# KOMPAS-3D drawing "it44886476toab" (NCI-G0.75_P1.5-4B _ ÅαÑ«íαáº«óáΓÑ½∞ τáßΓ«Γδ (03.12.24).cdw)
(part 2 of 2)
  Кривая без истории:10762
  Кривая без истории:10763
  Кривая без истории:10764
  Кривая без истории:10765
  Кривая без истории:10766
  Кривая без истории:10767
  Кривая без истории:10768
  Кривая без истории:10769
  Кривая без истории:10770
  Кривая без истории:10771
  Кривая без истории:10772
  Кривая без истории:10773
  Кривая без истории:10774
  Кривая без истории:10775
  Кривая без истории:10776
  Кривая без истории:10777
  Кривая без истории:10778
  Кривая без истории:10779
  Кривая без истории:10780
  Кривая без истории:10781
  Кривая без истории:10782
  Кривая без истории:10783
  Кривая без истории:10784
  Кривая без истории:10785
  Кривая без истории:10786
  Кривая без истории:10787
  Кривая без истории:10788
  Кривая без истории:10789
  Кривая без истории:10790
  Кривая без истории:10791
  Кривая без истории:10792
  Кривая без истории:10793
  Кривая без истории:10794
  Кривая без истории:10795
  Кривая без истории:10796
  Кривая без истории:10797
  Кривая без истории:10798
  Кривая без истории:10799
  Кривая без истории:10800
  Кривая без истории:10801
  Кривая без истории:10802
  Кривая без истории:10803
  Кривая без истории:10804
  Кривая без истории:10805
  Кривая без истории:10806
  Кривая без истории:10807
  Кривая без истории:10808
  Кривая без истории:10809
  Кривая без истории:10810
  Кривая без истории:10811
  Кривая без истории:10812
  Кривая без истории:10813
  Кривая без истории:10814
  Кривая без истории:10815
  Кривая без истории:10816
  Кривая без истории:10817
  Кривая без истории:10818
  Кривая без истории:10819
  Кривая без истории:10820
  Кривая без истории:10821
  Кривая без истории:10822
  Кривая без истории:10823
  Кривая без истории:10824
  Кривая без истории:10825
  Кривая без истории:10826
  Кривая без истории:10827
  Кривая без истории:10828
  Кривая без истории:10829
  Кривая без истории:10830
  Кривая без истории:10831
  Кривая без истории:10832
  Кривая без истории:10833
  Кривая без истории:10834
  Кривая без истории:10835
  Кривая без истории:10836
  Кривая без истории:10837
  Кривая без истории:10838
  Кривая без истории:10839
  Кривая без истории:10840
  Кривая без истории:10841
  Кривая без истории:10842
  Кривая без истории:10843
  Кривая без истории:10844
  Кривая без истории:10845
  Кривая без истории:10846
  Кривая без истории:10847
  Кривая без истории:10848
  Кривая без истории:10849
  Кривая без истории:10850
  Кривая без истории:10851
  Кривая без истории:10852
  Кривая без истории:10853
  Кривая без истории:10854
  Кривая без истории:10855
  Кривая без истории:10856
  Кривая без истории:10857
  Кривая без истории:10858
  Кривая без истории:10859
  Кривая без истории:10860
  Кривая без истории:10861
  Кривая без истории:10862
  Кривая без истории:10863
  Кривая без истории:10864
  Кривая без истории:10865
  Кривая без истории:10866
  Кривая без истории:10867
  Кривая без истории:10868
  Кривая без истории:10869
  Кривая без истории:10870
  Кривая без истории:10871
  Кривая без истории:10872
  Кривая без истории:10873
  Кривая без истории:10874
  Кривая без истории:10875
  Кривая без истории:10876
  Кривая без истории:10877
  Кривая без истории:10878
  Кривая без истории:10879
  Кривая без истории:10880
  Кривая без истории:10881
  Кривая без истории:10882
  Кривая без истории:10883
  Кривая без истории:10884
  Кривая без истории:10885
  Кривая без истории:10886
  Кривая без истории:10887
  Кривая без истории:10888
  Кривая без истории:10889
  Кривая без истории:10890
  Кривая без истории:10891
  Кривая без истории:10892
  Кривая без истории:10893
  Кривая без истории:10894
  Кривая без истории:10895
  Кривая без истории:10896
  Кривая без истории:10897
  Кривая без истории:10898
  Кривая без истории:10899
  Кривая без истории:10900
  Кривая без истории:10901
  Кривая без истории:10902
  Кривая без истории:10903
  Кривая без истории:10904
  Кривая без истории:10905
  Кривая без истории:10906
  Кривая без истории:10907
  Кривая без истории:10908
  Кривая без истории:10909
  Кривая без истории:10910
  Кривая без истории:10911
  Кривая без истории:10912
  Кривая без истории:10913
  Кривая без истории:10914
  Кривая без истории:10915
  Кривая без истории:10916
  Кривая без истории:10917
  Кривая без истории:10918
  Кривая без истории:10919
  Кривая без истории:10920
  Кривая без истории:10921
  Кривая без истории:10922
  Кривая без истории:10923
  Кривая без истории:10924
  Кривая без истории:10925
  Кривая без истории:10926
  Кривая без истории:10927
  Кривая без истории:10928
  Кривая без истории:10929
  Кривая без истории:10930
  Кривая без истории:10931
  Кривая без истории:10932
  Кривая без истории:10933
  Кривая без истории:10934
  Кривая без истории:10935
  Кривая без истории:10936
  Кривая без истории:10937
  Кривая без истории:10938
  Кривая без истории:10939
  Кривая без истории:10940
  Кривая без истории:10941
  Кривая без истории:10942
  Кривая без истории:10943
  Кривая без истории:10944
  Кривая без истории:10945
  Кривая без истории:10946
  Кривая без истории:10947
  Кривая без истории:10948
  Кривая без истории:10949
  Кривая без истории:10950
  Кривая без истории:10951
  Кривая без истории:10952
  Кривая без истории:10953
  Кривая без истории:10954
  Кривая без истории:10955
  Кривая без истории:10956
  Кривая без истории:10957
  Кривая без истории:10958
  Кривая без истории:10959
  Кривая без истории:10960
  Кривая без истории:10961
  Кривая без истории:10962
  Кривая без истории:10963
  Кривая без истории:10964
  Кривая без истории:10965
  Кривая без истории:10966
  Кривая без истории:10967
  Кривая без истории:10968
  Кривая без истории:10969
  Кривая без истории:10970
  Кривая без истории:10971
  Кривая без истории:10972
  Кривая без истории:10973
  Кривая без истории:10974
  Кривая без истории:10975
  Кривая без истории:10976
  Кривая без истории:10977
  Кривая без истории:10978
  Кривая без истории:10979
  Кривая без истории:10980
  Кривая без истории:10981
  Кривая без истории:10982
  Кривая без истории:10983
  Кривая без истории:10984
  Кривая без истории:10985
  Кривая без истории:10986
  Кривая без истории:10987
  Кривая без истории:10988
  Кривая без истории:10989
  Кривая без истории:10990
  Кривая без истории:10991
  Кривая без истории:10992
  Кривая без истории:10993
  Кривая без истории:10994
  Кривая без истории:10995
  Кривая без истории:10996
  Кривая без истории:10997
  Кривая без истории:10998
  Кривая без истории:10999
  Кривая без истории:11000
  Кривая без истории:11001
  Кривая без истории:11002
  Кривая без истории:11003
  Кривая без истории:11004
  Кривая без истории:11005
  Кривая без истории:11006
  Кривая без истории:11007
  Кривая без истории:11008
  Кривая без истории:11009
  Кривая без истории:11010
  Кривая без истории:11011
  Кривая без истории:11012
  Кривая без истории:11013
  Кривая без истории:11014
  Кривая без истории:11015
  Кривая без истории:11016
  Кривая без истории:11017
  Кривая без истории:11018
  Кривая без истории:11019
  Кривая без истории:11020
  Кривая без истории:11021
  Кривая без истории:11022
  Кривая без истории:11023
  Кривая без истории:11024
  Кривая без истории:11025
  Кривая без истории:11026
  Кривая без истории:11027
  Кривая без истории:11028
  Кривая без истории:11029
  Кривая без истории:11030
  Кривая без истории:11031
  Кривая без истории:11032
  Кривая без истории:11033
  Кривая без истории:11034
  Кривая без истории:11035
  Кривая без истории:11036
  Кривая без истории:11037
  Кривая без истории:11038
  Кривая без истории:11039
  Кривая без истории:11040
  Кривая без истории:11041
  Кривая без истории:11042
  Кривая без истории:11043
  Кривая без истории:11044
  Кривая без истории:11045
  Кривая без истории:11046
  Кривая без истории:11047
  Кривая без истории:11048
  Кривая без истории:11049
  Кривая без истории:11050
  Кривая без истории:11051
  Кривая без истории:11052
  Кривая без истории:11053
  Кривая без истории:11054
  Кривая без истории:11055
  Кривая без истории:11056
  Кривая без истории:11057
  Кривая без истории:11058
  Кривая без истории:11059
  Кривая без истории:11060
  Кривая без истории:11061
  Кривая без истории:11062
  Кривая без истории:11063
  Кривая без истории:11064
  Кривая без истории:11065
  Кривая без истории:11066
  Кривая без истории:11067
  Кривая без истории:11068
  Кривая без истории:11069
  Кривая без истории:11070
  Кривая без истории:11071
  Кривая без истории:11072
  Кривая без истории:11073
  Кривая без истории:11074
  Кривая без истории:11075
  Кривая без истории:11076
  Кривая без истории:11077
  Кривая без истории:11078
  Кривая без истории:11079
  Кривая без истории:11080
  Кривая без истории:11081
  Кривая без истории:11082
  Кривая без истории:11083
  Кривая без истории:11084
  Кривая без истории:11085
  Кривая без истории:11086
  Кривая без истории:11087
  Кривая без истории:11088
  Кривая без истории:11089
  Кривая без истории:11090
  Кривая без истории:11091
  Кривая без истории:11092
  Кривая без истории:11093
  Кривая без истории:11094
  Кривая без истории:11095
  Кривая без истории:11096
  Кривая без истории:11097
  Кривая без истории:11098
  Кривая без истории:11099
  Кривая без истории:11100
  Кривая без истории:11101
  Кривая без истории:11102
  Кривая без истории:11103
  Кривая без истории:11104
  Кривая без истории:11105
  Кривая без истории:11106
  Кривая без истории:11107
  Кривая без истории:11108
  Кривая без истории:11109
  Кривая без истории:11110
  Кривая без истории:11111
  Кривая без истории:11112
  Кривая без истории:11113
  Кривая без истории:11114
  Кривая без истории:11115
  Кривая без истории:11116
  Кривая без истории:11117
  Кривая без истории:11118
  Кривая без истории:11119
  Кривая без истории:11120
  Кривая без истории:11121
  Кривая без истории:11122
  Кривая без истории:11123
  Кривая без истории:11124
  Кривая без истории:11125
  Кривая без истории:11126
  Кривая без истории:11127
  Кривая без истории:11128
  Кривая без истории:11129
  Кривая без истории:11130
  Кривая без истории:11131
  Кривая без истории:11132
  Кривая без истории:11133
  Кривая без истории:11134
  Кривая без истории:11135
  Кривая без истории:11136
  Кривая без истории:11137
  Кривая без истории:11138
  Кривая без истории:11139
  Кривая без истории:11140
  Кривая без истории:11141
  Кривая без истории:11142
  Кривая без истории:11143
  Кривая без истории:11144
  Кривая без истории:11145
  Кривая без истории:11146
  Кривая без истории:11147
  Кривая без истории:11148
  Кривая без истории:11149
  Кривая без истории:11150
  Кривая без истории:11151
  Кривая без истории:11152
  Кривая без истории:11153
  Кривая без истории:11154
  Кривая без истории:11155
  Кривая без истории:11156
  Кривая без истории:11157
  Кривая без истории:11158
  Кривая без истории:11159
  Кривая без истории:11160
  Кривая без истории:11161
  Кривая без истории:11162
  Кривая без истории:11163
  Кривая без истории:11164
  Кривая без истории:11165
  Кривая без истории:11166
  Кривая без истории:11167
  Кривая без истории:11168
  Кривая без истории:11169
  Кривая без истории:11170
  Кривая без истории:11171
  Кривая без истории:11172
  Кривая без истории:11173
  Кривая без истории:11174
  Кривая без истории:11175
  Кривая без истории:11176
  Кривая без истории:11177
  Кривая без истории:11178
  Кривая без истории:11179
  Кривая без истории:11180
  Кривая без истории:11181
  Кривая без истории:11182
  Кривая без истории:11183
  Кривая без истории:11184
  Кривая без истории:11185
  Кривая без истории:11186
  Кривая без истории:11187
  Кривая без истории:11188
  Кривая без истории:11189
  Кривая без истории:11190
  Кривая без истории:11191
  Кривая без истории:11192
  Кривая без истории:11193
  Кривая без истории:11194
  Кривая без истории:11195
  Кривая без истории:11196
  Кривая без истории:11197
  Кривая без истории:11198
  Кривая без истории:11199
  Кривая без истории:11200
  Кривая без истории:11201
  Кривая без истории:11202
  Кривая без истории:11203
  Кривая без истории:11204
  Кривая без истории:11205
  Кривая без истории:11206
  Кривая без истории:11207
  Кривая без истории:11208
  Кривая без истории:11209
  Кривая без истории:11210
  Кривая без истории:11211
  Кривая без истории:11212
  Кривая без истории:11213
  Кривая без истории:11214
  Кривая без истории:11215
  Кривая без истории:11216
  Кривая без истории:11217
  Кривая без истории:11218
  Кривая без истории:11219
  Кривая без истории:11220
  Кривая без истории:11221
  Кривая без истории:11222
  Кривая без истории:11223
  Кривая без истории:11224
  Кривая без истории:11225
  Кривая без истории:11226
  Кривая без истории:11227
  Кривая без истории:11228
  Кривая без истории:11229
  Кривая без истории:11230
  Кривая без истории:11231
  Кривая без истории:11232
  Кривая без истории:11233
  Кривая без истории:11234
  Кривая без истории:11235
  Кривая без истории:11236
  Кривая без истории:11237
  Кривая без истории:11238
  Кривая без истории:11239
  Кривая без истории:11240
  Кривая без истории:11241
  Кривая без истории:11242
  Кривая без истории:11243
  Кривая без истории:11244
  Кривая без истории:11245
  Кривая без истории:11246
  Кривая без истории:11247
  Кривая без истории:11248
  Кривая без истории:11249
  Кривая без истории:11250
  Кривая без истории:11251
  Кривая без истории:11252
  Кривая без истории:11253
  Кривая без истории:11254
  Кривая без истории:11255
  Кривая без истории:11256
  Кривая без истории:11257
  Кривая без истории:11258
  Кривая без истории:11259
  Кривая без истории:11260
  Кривая без истории:11261
  Кривая без истории:11262
  Кривая без истории:11263
  Кривая без истории:11264
  Кривая без истории:11265
  Кривая без истории:11266
  Кривая без истории:11267
  Кривая без истории:11268
  Кривая без истории:11269
  Кривая без истории:11270
  Кривая без истории:11271
  Кривая без истории:11272
  Кривая без истории:11273
  Кривая без истории:11274
  Кривая без истории:11275
  Кривая без истории:11276
  Кривая без истории:11277
  Кривая без истории:11278
  Кривая без истории:11279
  Кривая без истории:11280
  Кривая без истории:11281
  Кривая без истории:11282
  Кривая без истории:11283
  Кривая без истории:11284
  Кривая без истории:11285
  Кривая без истории:11286
  Кривая без истории:11287
  Кривая без истории:11288
  Кривая без истории:11289
  Кривая без истории:11290
  Кривая без истории:11291
  Кривая без истории:11292
  Кривая без истории:11293
  Кривая без истории:11294
  Кривая без истории:11295
  Кривая без истории:11296
  Кривая без истории:11297
  Кривая без истории:11298
  Кривая без истории:11299
  Кривая без истории:11300
  Кривая без истории:11301
  Кривая без истории:11302
  Кривая без истории:11303
  Кривая без истории:11304
  Кривая без истории:11305
  Кривая без истории:11306
  Кривая без истории:11307
  Кривая без истории:11308
  Кривая без истории:11309
  Кривая без истории:11310
  Кривая без истории:11311
  Кривая без истории:11312
  Кривая без истории:11313
  Кривая без истории:11314
  Кривая без истории:11315
  Кривая без истории:11316
  Кривая без истории:11317
  Кривая без истории:11318
  Кривая без истории:11319
  Кривая без истории:11320
  Кривая без истории:11321
  Кривая без истории:11322
  Кривая без истории:11323
  Кривая без истории:11324
  Кривая без истории:11325
  Кривая без истории:11326
  Кривая без истории:11327
  Кривая без истории:11328
  Кривая без истории:11329
  Кривая без истории:11330
  Кривая без истории:11331
  Кривая без истории:11332
  Кривая без истории:11333
  Кривая без истории:11334
  Кривая без истории:11335
  Кривая без истории:11336
  Кривая без истории:11337
  Кривая без истории:11338
  Кривая без истории:11339
  Кривая без истории:11340
  Кривая без истории:11341
  Кривая без истории:11342
  Кривая без истории:11343
  Кривая без истории:11344
  Кривая без истории:11345
  Кривая без истории:11346
  Кривая без истории:11347
  Кривая без истории:11348
  Кривая без истории:11349
  Кривая без истории:11350
  Кривая без истории:11351
  Кривая без истории:11352
  Кривая без истории:11353
  Кривая без истории:11354
  Кривая без истории:11355
  Кривая без истории:11356
  Кривая без истории:11357
  Кривая без истории:11358
  Кривая без истории:11359
  Кривая без истории:11360
  Кривая без истории:11361
  Кривая без истории:11362
  Кривая без истории:11363
  Кривая без истории:11364
  Кривая без истории:11365
  Кривая без истории:11366
  Кривая без истории:11367
  Кривая без истории:11368
  Кривая без истории:11369
  Кривая без истории:11370
  Кривая без истории:11371
  Кривая без истории:11372
  Кривая без истории:11373
  Кривая без истории:11374
  Кривая без истории:11375
  Кривая без истории:11376
  Кривая без истории:11377
  Кривая без истории:11378
  Кривая без истории:11379
  Кривая без истории:11380
  Кривая без истории:11381
  Кривая без истории:11382
  Кривая без истории:11383
  Кривая без истории:11384
  Кривая без истории:11385
  Кривая без истории:11386
  Кривая без истории:11387
  Кривая без истории:11388
  Кривая без истории:11389
  Кривая без истории:11390
  Кривая без истории:11391
  Кривая без истории:11392
  Кривая без истории:11393
  Кривая без истории:11394
  Кривая без истории:11395
  Кривая без истории:11396
  Кривая без истории:11397
  Кривая без истории:11398
  Кривая без истории:11399
  Кривая без истории:11400
  Кривая без истории:11401
  Кривая без истории:11402
  Кривая без истории:11403
  Кривая без истории:11404
  Кривая без истории:11405
  Кривая без истории:11406
  Кривая без истории:11407
  Кривая без истории:11408
  Кривая без истории:11409
  Кривая без истории:11410
  Кривая без истории:11411
  Кривая без истории:11412
  Кривая без истории:11413
  Кривая без истории:11414
  Кривая без истории:11415
  Кривая без истории:11416
  Кривая без истории:11417
  Кривая без истории:11418
  Кривая без истории:11419
  Кривая без истории:11420
  Кривая без истории:11421
  Кривая без истории:11422
  Кривая без истории:11423
  Кривая без истории:11424
  Кривая без истории:11425
  Кривая без истории:11426
  Кривая без истории:11427
  Кривая без истории:11428
  Кривая без истории:11429
  Кривая без истории:11430
  Кривая без истории:11431
  Кривая без истории:11432
  Кривая без истории:11433
  Кривая без истории:11434
  Кривая без истории:11435
  Кривая без истории:11436
  Кривая без истории:11437
  Кривая без истории:11438
  Кривая без истории:11439
  Кривая без истории:11440
  Кривая без истории:11441
  Кривая без истории:11442
  Кривая без истории:11443
  Кривая без истории:11444
  Кривая без истории:11445
  Кривая без истории:11446
  Кривая без истории:11447
  Кривая без истории:11448
  Кривая без истории:11449
  Кривая без истории:11450
  Кривая без истории:11451
  Кривая без истории:11452
  Кривая без истории:11453
  Кривая без истории:11454
  Кривая без истории:11455
  Кривая без истории:11456
  Кривая без истории:11457
  Кривая без истории:11458
  Кривая без истории:11459
  Кривая без истории:11460
  Кривая без истории:11461
  Кривая без истории:11462
  Кривая без истории:11463
  Кривая без истории:11464
  Кривая без истории:11465
  Кривая без истории:11466
  Кривая без истории:11467
  Кривая без истории:11468
  Кривая без истории:11469
  Кривая без истории:11470
  Кривая без истории:11471
  Кривая без истории:11472
  Кривая без истории:11473
  Кривая без истории:11474
  Кривая без истории:11475
  Кривая без истории:11476
  Кривая без истории:11477
  Кривая без истории:11478
  Кривая без истории:11479
  Кривая без истории:11480
  Кривая без истории:11481
  Кривая без истории:11482
  Кривая без истории:11483
  Кривая без истории:11484
  Кривая без истории:11485
  Кривая без истории:11486
  Кривая без истории:11487
  Кривая без истории:11488
  Кривая без истории:11489
  Кривая без истории:11490
  Кривая без истории:11491
  Кривая без истории:11492
  Кривая без истории:11493
  Кривая без истории:11494
  Кривая без истории:11495
  Кривая без истории:11496
  Кривая без истории:11497
  Кривая без истории:11498
  Кривая без истории:11499
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Dimensions and other numbers on the sheet: 4±1; 1:1; 1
